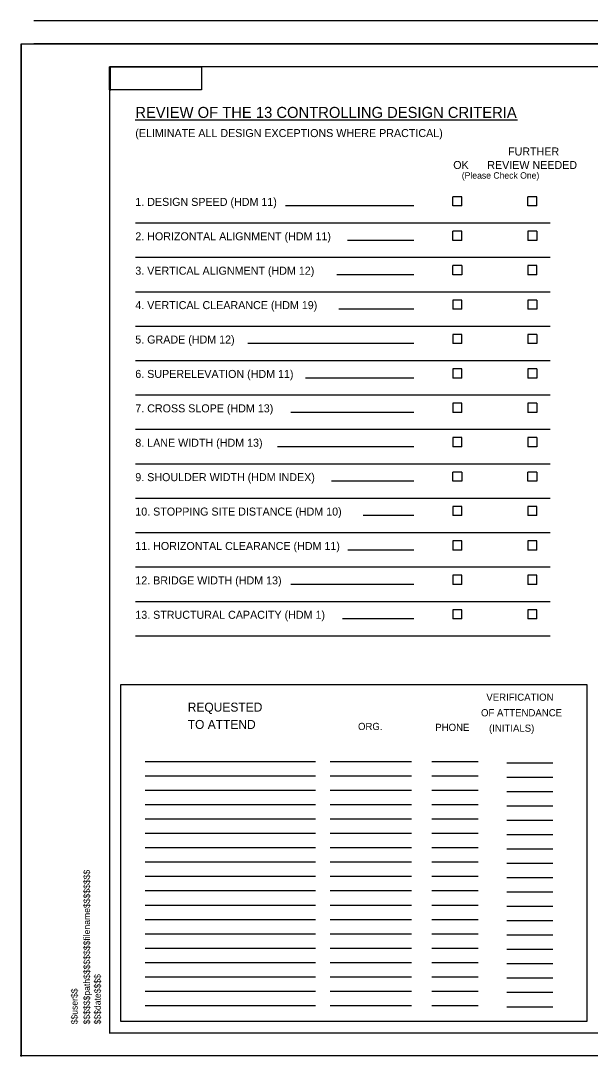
# Model space of a CAD drawing. Extents: x 160093 to 164626, y 177093 to 182727.
# Drawn here: x 161060 to 161679, y 178205 to 179330 of the extents above; entities that cross this region are included whole.
import ezdxf

# ---------------------------------------------------------------- set-up
doc = ezdxf.new("R2010")
doc.units = 0
for name, color, linetype in [('Level 38', 7, 'Continuous'), ('Level 40', 7, 'Continuous'), ('Level 41', 7, 'Continuous'), ('Level 42', 7, 'Continuous'), ('Level 43', 7, 'Continuous')]:
    doc.layers.add(name, color=color, linetype=linetype)

msp = doc.modelspace()

# ---------------------------------------------------------------- linework, layer by layer
at = {"layer": 'Level 38'}
for p, q in [((162833.7, 179330.3), (161073.7, 179330.3)), ((162833.7, 179305.3), (161073.7, 179305.3)), ((162831.1, 179280.3), (161156.1, 179280.3)), ((161156.1, 179280.3), (161156.1, 178229.5)), ((161156.7, 179279.4), (161156.7, 179254.4)), ((161599.6, 179222.1), (161183.9, 179222.1)), ((161539.2, 179138.9), (161529.2, 179138.9)), ((161529.2, 179128.9), (161529.2, 179138.9)), ((161539.2, 179128.9), (161539.2, 179138.9)), ((161620.7, 179138.9), (161610.7, 179138.9)), ((161610.7, 179128.9), (161610.7, 179138.9)), ((161620.7, 179128.9), (161620.7, 179138.9)), ((161487, 179128.9), (161347.4, 179128.9)), ((161539.2, 179128.9), (161529.2, 179128.9)), ((161620.7, 179128.9), (161610.7, 179128.9)), ((161635.1, 179110.2), (161184.4, 179110.2)), ((161539.2, 179101.5), (161529.2, 179101.5)), ((161529.2, 179091.5), (161529.2, 179101.5)), ((161539.2, 179091.5), (161539.2, 179101.5)), ((161620.7, 179101.5), (161610.7, 179101.5)), ((161610.7, 179101.5), (161610.7, 179091.5)), ((161620.7, 179101.5), (161620.7, 179091.5)), ((161487, 179091.5), (161414.6, 179091.5)), ((161539.2, 179091.5), (161529.2, 179091.5)), ((161620.7, 179091.5), (161610.7, 179091.5)), ((161635.1, 179072.8), (161184.4, 179072.8)), ((161539.2, 179064.1), (161529.2, 179064.1)), ((161529.2, 179054.1), (161529.2, 179064.1)), ((161539.2, 179064.1), (161539.2, 179054.1)), ((161620.7, 179064.1), (161610.7, 179064.1)), ((161610.7, 179064.1), (161610.7, 179054.1)), ((161620.7, 179054.1), (161620.7, 179064.1)), ((161487, 179054.1), (161403, 179054.1)), ((161539.2, 179054.1), (161529.2, 179054.1)), ((161620.7, 179054.1), (161610.7, 179054.1)), ((161635.1, 179035.4), (161184.4, 179035.4)), ((161487, 179016.7), (161405.4, 179016.7)), ((161539.2, 179026.7), (161529.2, 179026.7)), ((161529.2, 179026.7), (161529.2, 179016.7)), ((161539.2, 179016.7), (161529.2, 179016.7)), ((161539.2, 179016.7), (161539.2, 179026.7)), ((161620.7, 179026.7), (161610.7, 179026.7)), ((161610.7, 179026.7), (161610.7, 179016.7)), ((161620.7, 179016.7), (161610.7, 179016.7)), ((161620.7, 179026.7), (161620.7, 179016.7)), ((161635.1, 178998), (161184.4, 178998)), ((161539.2, 178989.3), (161529.2, 178989.3)), ((161529.2, 178989.3), (161529.2, 178979.3)), ((161539.2, 178979.3), (161539.2, 178989.3)), ((161620.7, 178989.3), (161610.7, 178989.3)), ((161610.7, 178989.3), (161610.7, 178979.3)), ((161620.7, 178989.3), (161620.7, 178979.3)), ((161487, 178979.3), (161306.4, 178979.3)), ((161539.2, 178979.3), (161529.2, 178979.3)), ((161620.7, 178979.3), (161610.7, 178979.3)), ((161635.1, 178960.6), (161184.4, 178960.6)), ((161539.2, 178951.9), (161529.2, 178951.9)), ((161529.2, 178951.9), (161529.2, 178941.9)), ((161539.2, 178941.9), (161539.2, 178951.9)), ((161620.7, 178951.9), (161610.7, 178951.9)), ((161610.7, 178951.9), (161610.7, 178941.9)), ((161620.7, 178951.9), (161620.7, 178941.9)), ((161487, 178941.9), (161369.1, 178941.9)), ((161539.2, 178941.9), (161529.2, 178941.9)), ((161620.7, 178941.9), (161610.7, 178941.9)), ((161635.1, 178923.2), (161184.4, 178923.2)), ((161487, 178904.5), (161353.2, 178904.5)), ((161539.2, 178914.5), (161529.2, 178914.5)), ((161529.2, 178914.5), (161529.2, 178904.5)), ((161539.2, 178904.5), (161529.2, 178904.5)), ((161539.2, 178904.5), (161539.2, 178914.5)), ((161620.7, 178914.5), (161610.7, 178914.5)), ((161610.7, 178914.5), (161610.7, 178904.5)), ((161620.7, 178904.5), (161610.7, 178904.5)), ((161620.7, 178914.5), (161620.7, 178904.5)), ((161635.1, 178885.8), (161184.4, 178885.8)), ((161539.2, 178877.1), (161529.2, 178877.1)), ((161529.2, 178877.1), (161529.2, 178867.1)), ((161539.2, 178867.1), (161539.2, 178877.1)), ((161620.7, 178877.1), (161610.7, 178877.1)), ((161610.7, 178877.1), (161610.7, 178867.1)), ((161620.7, 178877.1), (161620.7, 178867.1)), ((161487, 178867.1), (161338.8, 178867.1)), ((161539.2, 178867.1), (161529.2, 178867.1)), ((161620.7, 178867.1), (161610.7, 178867.1)), ((161635.1, 178848.4), (161184.4, 178848.4)), ((161539.2, 178839.7), (161529.2, 178839.7)), ((161529.2, 178829.7), (161529.2, 178839.7)), ((161539.2, 178839.7), (161539.2, 178829.7)), ((161620.7, 178839.7), (161610.7, 178839.7)), ((161610.7, 178829.7), (161610.7, 178839.7)), ((161620.7, 178839.7), (161620.7, 178829.7)), ((161487, 178829.7), (161397.2, 178829.7)), ((161539.2, 178829.7), (161529.2, 178829.7)), ((161620.7, 178829.7), (161610.7, 178829.7)), ((161635.1, 178811), (161184.4, 178811)), ((161487, 178792.3), (161431.7, 178792.3)), ((161539.2, 178802.3), (161529.2, 178802.3)), ((161529.2, 178802.3), (161529.2, 178792.3)), ((161539.2, 178792.3), (161529.2, 178792.3)), ((161539.2, 178792.3), (161539.2, 178802.3)), ((161620.7, 178802.3), (161610.7, 178802.3)), ((161610.7, 178802.3), (161610.7, 178792.3)), ((161620.7, 178792.3), (161610.7, 178792.3)), ((161620.7, 178792.3), (161620.7, 178802.3)), ((161635.1, 178773.6), (161184.4, 178773.6)), ((161539.2, 178764.9), (161529.2, 178764.9)), ((161529.2, 178764.9), (161529.2, 178754.9)), ((161539.2, 178754.9), (161539.2, 178764.9)), ((161620.7, 178764.9), (161610.7, 178764.9)), ((161610.7, 178764.9), (161610.7, 178754.9)), ((161620.7, 178754.9), (161620.7, 178764.9)), ((161487, 178754.9), (161415.2, 178754.9)), ((161539.2, 178754.9), (161529.2, 178754.9)), ((161620.7, 178754.9), (161610.7, 178754.9)), ((161635.1, 178736.2), (161184.4, 178736.2)), ((161539.2, 178727.5), (161529.2, 178727.5)), ((161529.2, 178727.5), (161529.2, 178717.5)), ((161539.2, 178717.5), (161539.2, 178727.5)), ((161620.7, 178727.5), (161610.7, 178727.5)), ((161610.7, 178727.5), (161610.7, 178717.5)), ((161620.7, 178717.5), (161620.7, 178727.5)), ((161487, 178717.5), (161353.2, 178717.5)), ((161539.2, 178717.5), (161529.2, 178717.5)), ((161620.7, 178717.5), (161610.7, 178717.5)), ((161635.1, 178698.8), (161184.4, 178698.8)), ((161539.2, 178690.1), (161529.2, 178690.1)), ((161529.2, 178690.1), (161529.2, 178680.1)), ((161539.2, 178680.1), (161539.2, 178690.1)), ((161620.7, 178690.1), (161610.7, 178690.1)), ((161610.7, 178690.1), (161610.7, 178680.1)), ((161620.7, 178680.1), (161620.7, 178690.1)), ((161487, 178680.1), (161409.4, 178680.1)), ((161539.2, 178680.1), (161529.2, 178680.1)), ((161620.7, 178680.1), (161610.7, 178680.1)), ((161635.1, 178661.4), (161184.4, 178661.4)), ((161195, 178525.1), (161380.1, 178525.1)), ((161396.1, 178525.1), (161484.3, 178525.1)), ((161506.5, 178525.1), (161556.9, 178525.1)), ((161587.8, 178523.8), (161638.1, 178523.8)), ((161195, 178509.5), (161380.1, 178509.5)), ((161396.1, 178509.5), (161484.3, 178509.5)), ((161506.5, 178509.5), (161556.9, 178509.5)), ((161587.8, 178508.2), (161638.1, 178508.2)), ((161195, 178493.9), (161380.1, 178493.9)), ((161396.1, 178493.9), (161484.3, 178493.9)), ((161506.5, 178493.9), (161556.9, 178493.9)), ((161587.8, 178492.6), (161638.1, 178492.6)), ((161195, 178478.3), (161380.1, 178478.3)), ((161396.1, 178478.3), (161484.3, 178478.3)), ((161506.5, 178478.3), (161556.9, 178478.3)), ((161587.8, 178477), (161638.1, 178477)), ((161195, 178462.7), (161380.1, 178462.7)), ((161396.1, 178462.7), (161484.3, 178462.7)), ((161506.5, 178462.7), (161556.9, 178462.7)), ((161587.8, 178461.4), (161638.1, 178461.4)), ((161195, 178447.1), (161380.1, 178447.1)), ((161396.1, 178447.1), (161484.3, 178447.1)), ((161506.5, 178447.1), (161556.9, 178447.1)), ((161587.8, 178445.8), (161638.1, 178445.8)), ((161195, 178431.5), (161380.1, 178431.5)), ((161396.1, 178431.5), (161484.3, 178431.5)), ((161506.5, 178431.5), (161556.9, 178431.5)), ((161587.8, 178430.2), (161638.1, 178430.2)), ((161195, 178415.9), (161380.1, 178415.9)), ((161396.1, 178415.9), (161484.3, 178415.9)), ((161506.5, 178415.9), (161556.9, 178415.9)), ((161587.8, 178414.6), (161638.1, 178414.6)), ((161195, 178400.3), (161380.1, 178400.3)), ((161396.1, 178400.3), (161484.3, 178400.3)), ((161506.5, 178400.3), (161556.9, 178400.3)), ((161587.8, 178399), (161638.1, 178399)), ((161195, 178384.7), (161380.1, 178384.7)), ((161396.1, 178384.7), (161484.3, 178384.7)), ((161506.5, 178384.7), (161556.9, 178384.7)), ((161587.8, 178383.4), (161638.1, 178383.4)), ((161195, 178369.1), (161380.1, 178369.1)), ((161396.1, 178369.1), (161484.3, 178369.1)), ((161506.5, 178369.1), (161556.9, 178369.1)), ((161587.8, 178367.8), (161638.1, 178367.8)), ((161195, 178353.5), (161380.1, 178353.5)), ((161396.1, 178353.5), (161484.3, 178353.5)), ((161506.5, 178353.5), (161556.9, 178353.5)), ((161587.8, 178352.2), (161638.1, 178352.2)), ((161195, 178337.9), (161380.1, 178337.9)), ((161396.1, 178337.9), (161484.3, 178337.9)), ((161506.5, 178337.9), (161556.9, 178337.9)), ((161587.8, 178336.6), (161638.1, 178336.6)), ((161195, 178322.3), (161380.1, 178322.3)), ((161396.1, 178322.3), (161484.3, 178322.3)), ((161506.5, 178322.3), (161556.9, 178322.3)), ((161587.8, 178321), (161638.1, 178321)), ((161195, 178306.7), (161380.1, 178306.7)), ((161396.1, 178306.7), (161484.3, 178306.7)), ((161506.5, 178306.7), (161556.9, 178306.7)), ((161587.8, 178305.4), (161638.1, 178305.4)), ((161195, 178291.1), (161380.1, 178291.1)), ((161396.1, 178291.1), (161484.3, 178291.1)), ((161506.5, 178291.1), (161556.9, 178291.1)), ((161587.8, 178289.8), (161638.1, 178289.8)), ((161195, 178275.5), (161380.1, 178275.5)), ((161396.1, 178275.5), (161484.3, 178275.5)), ((161506.5, 178275.5), (161556.9, 178275.5)), ((161587.8, 178274.2), (161638.1, 178274.2)), ((161195, 178259.9), (161380.1, 178259.9)), ((161396.1, 178259.9), (161484.3, 178259.9)), ((161506.5, 178259.9), (161556.9, 178259.9)), ((161587.8, 178258.6), (161638.1, 178258.6)), ((161156.1, 178230.3), (162831.1, 178230.3)), ((162833.7, 178205.3), (161073.7, 178205.3))]:
    msp.add_line(p, q, dxfattribs=at)
for points in [[(161156.2, 179255.3), (161156.2, 179280.3), (161256.2, 179280.3), (161256.2, 179255.3)], [(161167.9, 178608.3), (161167.9, 178242.9), (161675.4, 178242.9), (161675.4, 178608.3)]]:
    msp.add_lwpolyline(points, close=True, dxfattribs=at)
at = {"layer": 'Level 42'}
msp.add_lwpolyline([(161060.1, 179305.3), (162856.1, 179305.3), (162856.1, 178205.3), (161060.1, 178205.3)], close=True, dxfattribs=at)
at = {"layer": 'Level 43'}
msp.add_line((161060.1, 179305.3), (161060.1, 178205.3), dxfattribs=at)
msp.add_circle((161060.1, 178205.3), 0.607, dxfattribs=at)
msp.add_circle((161060.1, 178205.3), 0.607, dxfattribs=at)

# ---------------------------------------------------------------- texts
at = {"layer": 'Level 40'}
for s, height, p in [('REVIEW OF THE 13 CONTROLLING DESIGN CRITERIA', 12, (161184.1, 179224.6)), ('(ELIMINATE ALL DESIGN EXCEPTIONS WHERE PRACTICAL)', 8.7, (161184.1, 179203.8)), ('FURTHER', 8.7, (161589.3, 179183.8)), ('OK', 8.7, (161529.7, 179169.1)), ('REVIEW NEEDED', 8.7, (161566.7, 179169.1)), ('(Please Check One)', 7, (161539, 179158.6)), ('1. DESIGN SPEED (HDM 11)', 8.7, (161184.1, 179129)), ('2. HORIZONTAL ALIGNMENT (HDM 11)', 8.7, (161184.1, 179091.6)), ('3. VERTICAL ALIGNMENT (HDM 12)', 8.7, (161184.1, 179054.2)), ('4. VERTICAL CLEARANCE (HDM 19)', 8.7, (161184.1, 179016.8)), ('5. GRADE (HDM 12)', 8.7, (161184.1, 178979.4)), ('6. SUPERELEVATION (HDM 11)', 8.7, (161184.1, 178942)), ('7. CROSS SLOPE (HDM 13)', 8.7, (161184.1, 178904.6)), ('8. LANE WIDTH (HDM 13)', 8.7, (161184.1, 178867.2)), ('9. SHOULDER WIDTH (HDM INDEX)', 8.7, (161184.1, 178829.8)), ('10. STOPPING SITE DISTANCE (HDM 10)', 8.7, (161184.1, 178792.4)), ('11. HORIZONTAL CLEARANCE (HDM 11)', 8.7, (161184.1, 178755)), ('12. BRIDGE WIDTH (HDM 13)', 8.7, (161184.1, 178717.6)), ('13. STRUCTURAL CAPACITY (HDM 1)', 8.7, (161184.1, 178680.2)), ('REQUESTED ', 9.75, (161241.1, 178579.3)), ('  VERIFICATION ', 7.8, (161559.9, 178591.1)), ('OF ATTENDANCE', 7.8, (161559.9, 178574.2)), ('TO ATTEND', 9.75, (161241.1, 178560.5)), ('ORG.', 7.8, (161426.2, 178559.3)), ('PHONE', 7.8, (161510.2, 178558.3)), ('   (INITIALS)', 7.8, (161559.9, 178557.4))]:
    msp.add_text(s, height=height, dxfattribs=at).set_placement(p)
at = {"layer": 'Level 41'}
for s, p in [('$$$$$$path$$$$$$$$filename$$$$$$$$', (161134.8, 178239.3)), ('$$$date$$$$', (161146.5, 178239.3)), ('$$user$$', (161121.4, 178239.4))]:
    msp.add_text(s, height=7, rotation=90, dxfattribs=at).set_placement(p)

doc.saveas('drawing.dxf')
